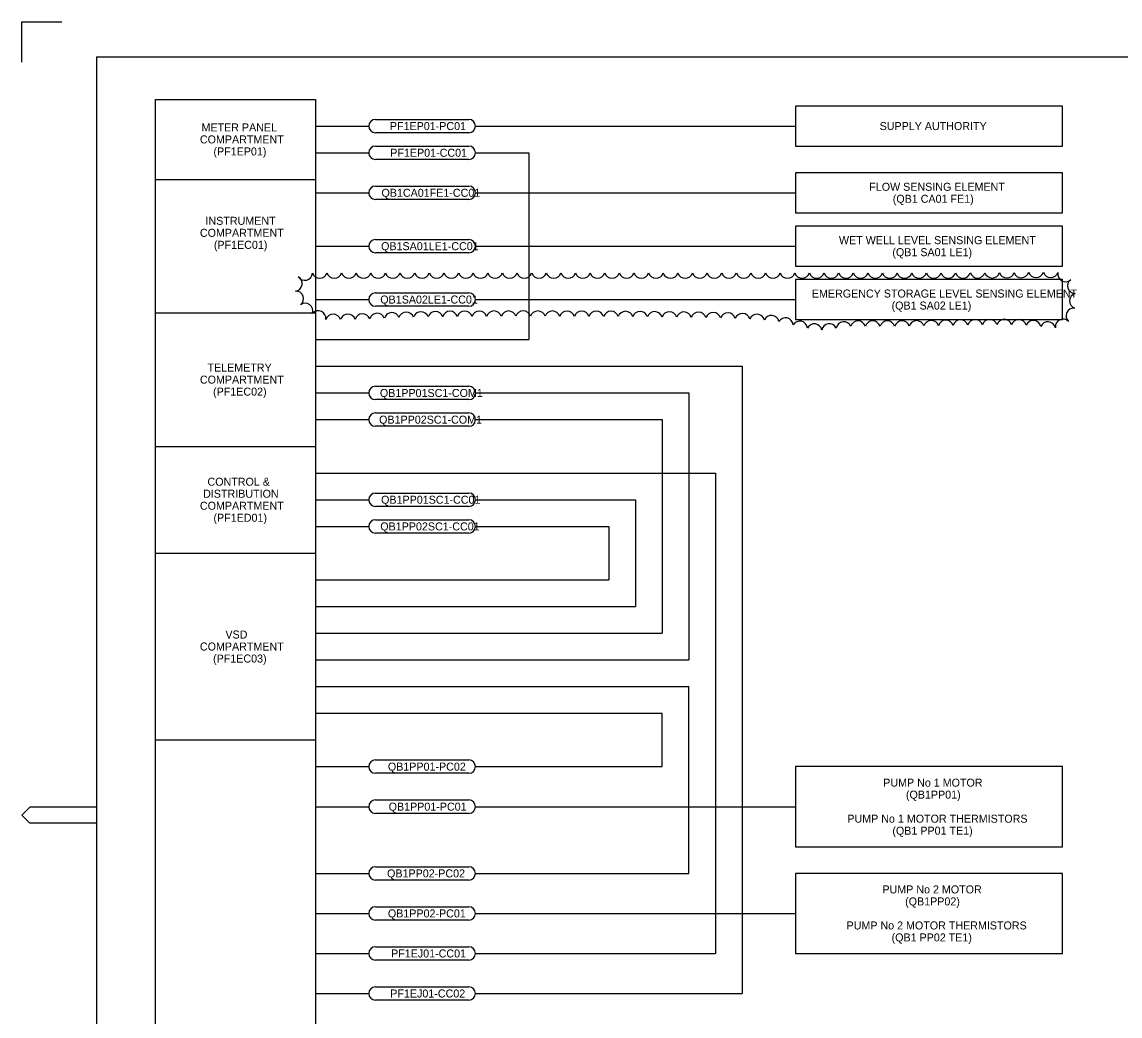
# Model space of a CAD drawing. Extents: x 0 to 841, y 0 to 594.
# Drawn here: x 0 to 411.6, y 221.6 to 594 of the extents above; entities that cross this region are included whole.
import ezdxf

# ---------------------------------------------------------------- set-up
doc = ezdxf.new("R2010")
doc.units = 0
for name, color, linetype in [('A1BORDER', 7, 'Continuous'), ('Default', 7, 'Continuous'), ('INSTALLED', 7, 'Continuous'), ('Level 1', 7, 'Continuous')]:
    doc.layers.add(name, color=color, linetype=linetype)

msp = doc.modelspace()

# ---------------------------------------------------------------- linework, layer by layer
at = {"layer": 'A1BORDER'}
for p, q in [((0, 594), (15, 594)), ((0, 579), (0, 594)), ((28, 581), (829, 581)), ((28, 581), (28, 15)), ((3, 299.76), (0, 296.76)), ((3, 293.76), (0, 296.76)), ((28, 299.76), (3, 299.76)), ((28, 293.76), (3, 293.76))]:
    msp.add_line(p, q, dxfattribs=at)
at = {"layer": 'Default'}
for p, q in [((190, 545), (190, 475)), ((50, 535), (110, 535)), ((170, 510), (290, 510)), ((50, 485), (110, 485)), ((270, 465), (270, 230)), ((170, 455), (250, 455)), ((250, 455), (250, 355)), ((170, 445), (240, 445)), ((240, 445), (240, 365)), ((50, 435), (110, 435)), ((170, 415), (230, 415)), ((230, 415), (230, 375)), ((170, 405), (220, 405)), ((220, 405), (220, 385)), ((50, 395), (110, 395)), ((250, 275), (250, 345)), ((240, 315), (240, 335)), ((50, 325), (110, 325))]:
    msp.add_line(p, q, dxfattribs=at)
at = {"layer": 'INSTALLED'}
for p, q in [((132.5, 557.5), (167.5, 557.5)), ((110, 555), (130, 555)), ((167.5, 552.5), (132.5, 552.5)), ((170, 555), (290, 555)), ((132.5, 547.5), (167.5, 547.5)), ((110, 545), (130, 545)), ((170, 545), (190, 545)), ((167.5, 542.5), (132.5, 542.5)), ((132.5, 532.5), (167.5, 532.5)), ((110, 530), (130, 530)), ((167.5, 527.5), (132.5, 527.5)), ((170, 530), (290, 530)), ((132.5, 512.5), (167.5, 512.5)), ((110, 510), (130, 510)), ((167.5, 507.5), (132.5, 507.5)), ((110, 490), (130, 490)), ((132.5, 492.5), (167.5, 492.5)), ((170, 490), (290, 490)), ((167.5, 487.5), (132.5, 487.5)), ((110, 475), (190, 475)), ((110, 465), (270, 465)), ((132.5, 457.5), (167.5, 457.5)), ((110, 455), (130, 455)), ((167.5, 452.5), (132.5, 452.5)), ((110, 445), (130, 445)), ((132.5, 447.5), (167.5, 447.5)), ((167.5, 442.5), (132.5, 442.5)), ((110, 425), (260, 425)), ((132.5, 417.5), (167.5, 417.5)), ((110, 415), (130, 415)), ((167.5, 412.5), (132.5, 412.5)), ((132.5, 407.5), (167.5, 407.5)), ((110, 405), (130, 405)), ((167.5, 402.5), (132.5, 402.5)), ((110, 385), (220, 385)), ((110, 375), (230, 375)), ((110, 365), (240, 365)), ((110, 355), (250, 355)), ((110, 345), (250, 345)), ((110, 335), (240, 335)), ((132.5, 317.5), (167.5, 317.5)), ((110, 315), (130, 315)), ((170, 315), (240, 315)), ((167.5, 312.5), (132.5, 312.5)), ((132.5, 302.5), (167.5, 302.5)), ((110, 300), (130, 300)), ((167.5, 297.5), (132.5, 297.5)), ((170, 300), (290, 300)), ((132.5, 277.5), (167.5, 277.5)), ((110, 275), (130, 275)), ((167.5, 272.5), (132.5, 272.5)), ((170, 275), (250, 275)), ((110, 260), (130, 260)), ((132.5, 262.5), (167.5, 262.5)), ((170, 260), (290, 260)), ((167.5, 257.5), (132.5, 257.5)), ((132.5, 247.5), (167.5, 247.5)), ((110, 245), (130, 245)), ((170, 245), (260, 245)), ((167.5, 242.5), (132.5, 242.5)), ((132.5, 232.5), (167.5, 232.5)), ((110, 230), (130, 230)), ((167.5, 227.5), (132.5, 227.5)), ((170, 230), (270, 230))]:
    msp.add_line(p, q, dxfattribs=at)
for points in [[(50, 565), (110, 565), (110, 75), (50, 75)], [(290, 547.5), (390, 547.5), (390, 562.5), (290, 562.5)], [(290, 522.5), (390, 522.5), (390, 537.5), (290, 537.5)], [(290, 502.5), (390, 502.5), (390, 517.5), (290, 517.5)], [(290, 482.5), (390, 482.5), (390, 497.5), (290, 497.5)], [(290, 285), (390, 285), (390, 315), (290, 315)], [(290, 245), (390, 245), (390, 275), (290, 275)]]:
    msp.add_lwpolyline(points, close=True, dxfattribs=at)
for centre, start, end in [((132.5, 555), 90, 270), ((167.5, 555), 270, 90), ((132.5, 545), 90, 270), ((167.5, 545), 270, 90), ((132.5, 530), 90, 270), ((167.5, 530), 270, 90), ((132.5, 510), 90, 270), ((167.5, 510), 270, 90), ((132.5, 490), 90, 270), ((167.5, 490), 270, 90), ((132.5, 455), 90, 270), ((167.5, 455), 270, 90), ((132.5, 445), 90, 270), ((167.5, 445), 270, 90), ((132.5, 415), 90, 270), ((167.5, 415), 270, 90), ((132.5, 405), 90, 270), ((167.5, 405), 270, 90), ((132.5, 315), 90, 270), ((167.5, 315), 270, 90), ((132.5, 300), 90, 270), ((167.5, 300), 270, 90), ((132.5, 275), 90, 270), ((167.5, 275), 270, 90), ((132.5, 260), 90, 270), ((167.5, 260), 270, 90), ((132.5, 245), 90, 270), ((167.5, 245), 270, 90), ((132.5, 230), 90, 270), ((167.5, 230), 270, 90)]:
    msp.add_arc(centre, 2.5, start, end, dxfattribs=at)
at = {"layer": 'Level 1'}
msp.add_line((260, 425), (260, 245), dxfattribs=at)
for centre, start, end in [((102.18, 496.01), 276.4341, 61.4341), ((105.98, 500.07), 212.4173, 357.4173), ((111.58, 500.84), 198.0744, 343.0744), ((117.07, 500.86), 197.5, 342.5), ((122.55, 500.86), 197.5, 342.5), ((128.03, 500.86), 197.5, 342.5), ((133.51, 500.86), 197.5, 342.5), ((138.99, 500.86), 197.5, 342.5), ((144.47, 500.86), 197.5, 342.5), ((149.95, 500.86), 197.5, 342.5), ((155.43, 500.86), 197.5, 342.5), ((160.91, 500.86), 197.5, 342.5), ((166.39, 500.86), 197.5, 342.5), ((171.87, 500.86), 197.5, 342.5), ((177.35, 500.86), 197.5, 342.5), ((182.83, 500.86), 197.5, 342.5), ((188.31, 500.86), 197.5, 342.5), ((193.79, 500.86), 197.5, 342.5), ((199.27, 500.86), 197.5, 342.5), ((204.75, 500.86), 197.5, 342.5), ((210.23, 500.86), 197.5, 342.5), ((215.7, 500.86), 197.5, 342.5), ((221.18, 500.86), 197.5, 342.5), ((226.66, 500.86), 197.5001, 342.5001), ((232.14, 500.86), 197.5003, 342.5003), ((237.62, 500.86), 197.5005, 342.5005), ((243.1, 500.86), 197.5007, 342.5007), ((248.58, 500.86), 197.501, 342.501), ((254.06, 500.86), 197.5012, 342.5012), ((259.54, 500.86), 197.5015, 342.5015), ((265.02, 500.86), 197.5018, 342.5018), ((270.5, 500.86), 197.5021, 342.5021), ((275.98, 500.86), 197.5025, 342.5025), ((281.46, 500.87), 197.5029, 342.5029), ((286.94, 500.87), 197.5034, 342.5034), ((292.42, 500.87), 197.5039, 342.5039), ((297.9, 500.87), 197.5045, 342.5045), ((303.38, 500.87), 197.5052, 342.5052), ((308.86, 500.87), 197.5061, 342.5061), ((314.34, 500.87), 197.5071, 342.5071), ((319.82, 500.87), 197.5084, 342.5084), ((325.3, 500.87), 197.51, 342.51), ((330.78, 500.87), 197.5123, 342.5123), ((336.26, 500.87), 197.5158, 342.5158), ((341.74, 500.87), 197.5221, 342.5221), ((347.22, 500.88), 197.5432, 342.5432), ((352.7, 500.88), 197.611, 342.611), ((358.17, 500.9), 197.7082, 342.7082), ((363.65, 500.93), 197.8496, 342.8496), ((369.13, 500.97), 198.0843, 343.0843), ((374.6, 501.04), 198.4189, 343.4189), ((380.09, 501.11), 197.9553, 342.9553), ((385.59, 501.07), 196.3358, 341.3358), ((391.12, 499.55), 167.8046, 312.8046), ((394.76, 495.11), 125.9223, 270.9223), ((102.69, 490.29), 308.7307, 93.7307), ((395.55, 489.47), 105.0972, 250.0972), ((106.2, 485.75), 341.74, 126.74), ((111.06, 482.93), 352.9566, 137.9566), ((165.96, 482.8), 17.9331, 162.9331), ((171.44, 482.83), 17.7855, 162.7855), ((176.92, 482.85), 17.6642, 162.6642), ((182.39, 482.86), 17.5623, 162.5623), ((187.87, 482.87), 17.484, 162.484), ((193.35, 482.86), 17.4282, 162.4282), ((198.83, 482.85), 17.3711, 162.3711), ((204.31, 482.84), 17.3122, 162.3122), ((209.79, 482.82), 17.2512, 162.2512), ((394.22, 483.92), 82.8541, 227.8541), ((116.64, 481.67), 16.7255, 161.7255), ((122.15, 481.67), 18.2205, 163.2205), ((127.64, 481.8), 19.5074, 164.5074), ((133.12, 482.01), 19.879, 164.879), ((138.6, 482.24), 19.9247, 164.9247), ((144.06, 482.44), 19.2115, 164.2115), ((149.53, 482.58), 18.6974, 163.6974), ((155.01, 482.68), 18.3608, 163.3608), ((160.48, 482.75), 18.1185, 163.1185), ((215.27, 482.79), 17.188, 162.188), ((220.75, 482.76), 17.1225, 162.1225), ((226.22, 482.72), 17.0546, 162.0546), ((231.7, 482.67), 16.9841, 161.9841), ((237.18, 482.62), 16.9108, 161.9108), ((242.66, 482.56), 16.8345, 161.8345), ((248.14, 482.49), 16.7486, 161.7486), ((253.61, 482.41), 16.5203, 161.5203), ((259.09, 482.3), 16.1729, 161.1729), ((264.56, 482.15), 15.7029, 160.7029), ((270.02, 481.94), 15.0153, 160.0153), ((275.48, 481.65), 13.8616, 158.8616), ((280.89, 481.18), 11.2015, 156.2015), ((286.2, 480.3), 4.8648, 149.8648), ((291.52, 479.06), 4.055, 149.055), ((308.05, 478.81), 24.3829, 169.3829), ((313.41, 479.14), 17.5, 162.5), ((318.88, 479.14), 17.5, 162.5), ((324.37, 479.14), 17.5655, 162.5655), ((329.85, 479.16), 17.9507, 162.9507), ((335.33, 479.22), 18.2448, 163.2448), ((340.82, 479.3), 18.45, 163.45), ((346.3, 479.4), 18.6036, 163.6036), ((351.78, 479.51), 18.7243, 163.7243), ((357.26, 479.63), 18.676, 163.676), ((362.73, 479.71), 18.1186, 163.1186), ((368.19, 479.73), 17.2608, 162.2608), ((373.65, 479.64), 15.7929, 160.7929), ((379.06, 479.31), 12.2051, 157.2051), ((384.53, 478.82), 12.7041, 157.7041), ((390.18, 479.84), 42.6678, 187.6678), ((296.98, 478.02), 9.3201, 154.3201), ((302.65, 478.06), 26.4945, 171.4945)]:
    msp.add_arc(centre, 2.87, start, end, dxfattribs=at)

# ---------------------------------------------------------------- texts
at = {"layer": 'INSTALLED'}
for s, p in [('METER PANEL', (67.3, 553)), ('PF1EP01-PC01', (137.9, 553.5)), ('SUPPLY AUTHORITY', (321.47, 553.5)), ('COMPARTMENT', (66.7, 548.5)), ('(PF1EP01)', (71.78, 544)), ('PF1EP01-CC01', (138.05, 543.5)), ('QB1CA01FE1-CC01', (134.76, 528.5)), ('FLOW SENSING ELEMENT', (317.59, 530.75)), ('(QB1 CA01 FE1)', (326.4, 526.25)), ('INSTRUMENT', (68.79, 518)), ('COMPARTMENT', (66.7, 513.5)), ('(PF1EC01)', (71.93, 509)), ('QB1SA01LE1-CC01', (134.61, 508.5)), ('WET WELL LEVEL SENSING ELEMENT', (306.23, 510.75)), ('(QB1 SA01 LE1)', (326.25, 506.25)), ('QB1SA02LE1-CC01', (134.31, 488.5)), ('EMERGENCY STORAGE LEVEL SENSING ELEMENT', (296.07, 490.75)), ('(QB1 SA02 LE1)', (325.96, 486.25)), ('TELEMETRY', (69.54, 463)), ('COMPARTMENT', (66.7, 458.5)), ('(PF1EC02)', (71.63, 454)), ('QB1PP01SC1-COM1', (134.16, 453.5)), ('QB1PP02SC1-COM1', (133.86, 443.5)), ('CONTROL &', (69.54, 420.25)), ('DISTRIBUTION', (67.9, 415.75)), ('QB1PP01SC1-CC01', (134.61, 413.5)), ('COMPARTMENT', (66.7, 411.25)), ('(PF1ED01)', (71.78, 406.75)), ('QB1PP02SC1-CC01', (134.31, 403.5)), ('VSD', (76.26, 363)), ('COMPARTMENT', (66.7, 358.5)), ('(PF1EC03)', (71.63, 354)), ('QB1PP01-PC02', (137.15, 313.5)), ('PUMP No 1 MOTOR', (322.82, 307.5)), ('(QB1PP01)', (331.33, 303)), ('QB1PP01-PC01', (137.45, 298.5)), ('PUMP No 1 MOTOR THERMISTORS', (309.37, 294)), ('(QB1 PP01 TE1)', (326.25, 289.5)), ('QB1PP02-PC02', (136.85, 273.5)), ('PUMP No 2 MOTOR', (322.52, 267.5)), ('(QB1PP02)', (331.04, 263)), ('QB1PP02-PC01', (137.15, 258.5)), ('PUMP No 2 MOTOR THERMISTORS', (309.07, 254)), ('(QB1 PP02 TE1)', (325.96, 249.5)), ('PF1EJ01-CC01', (138.35, 243.5)), ('PF1EJ01-CC02', (138.05, 228.5))]:
    msp.add_text(s, height=3, dxfattribs=at).set_placement(p)

doc.saveas('drawing.dxf')
